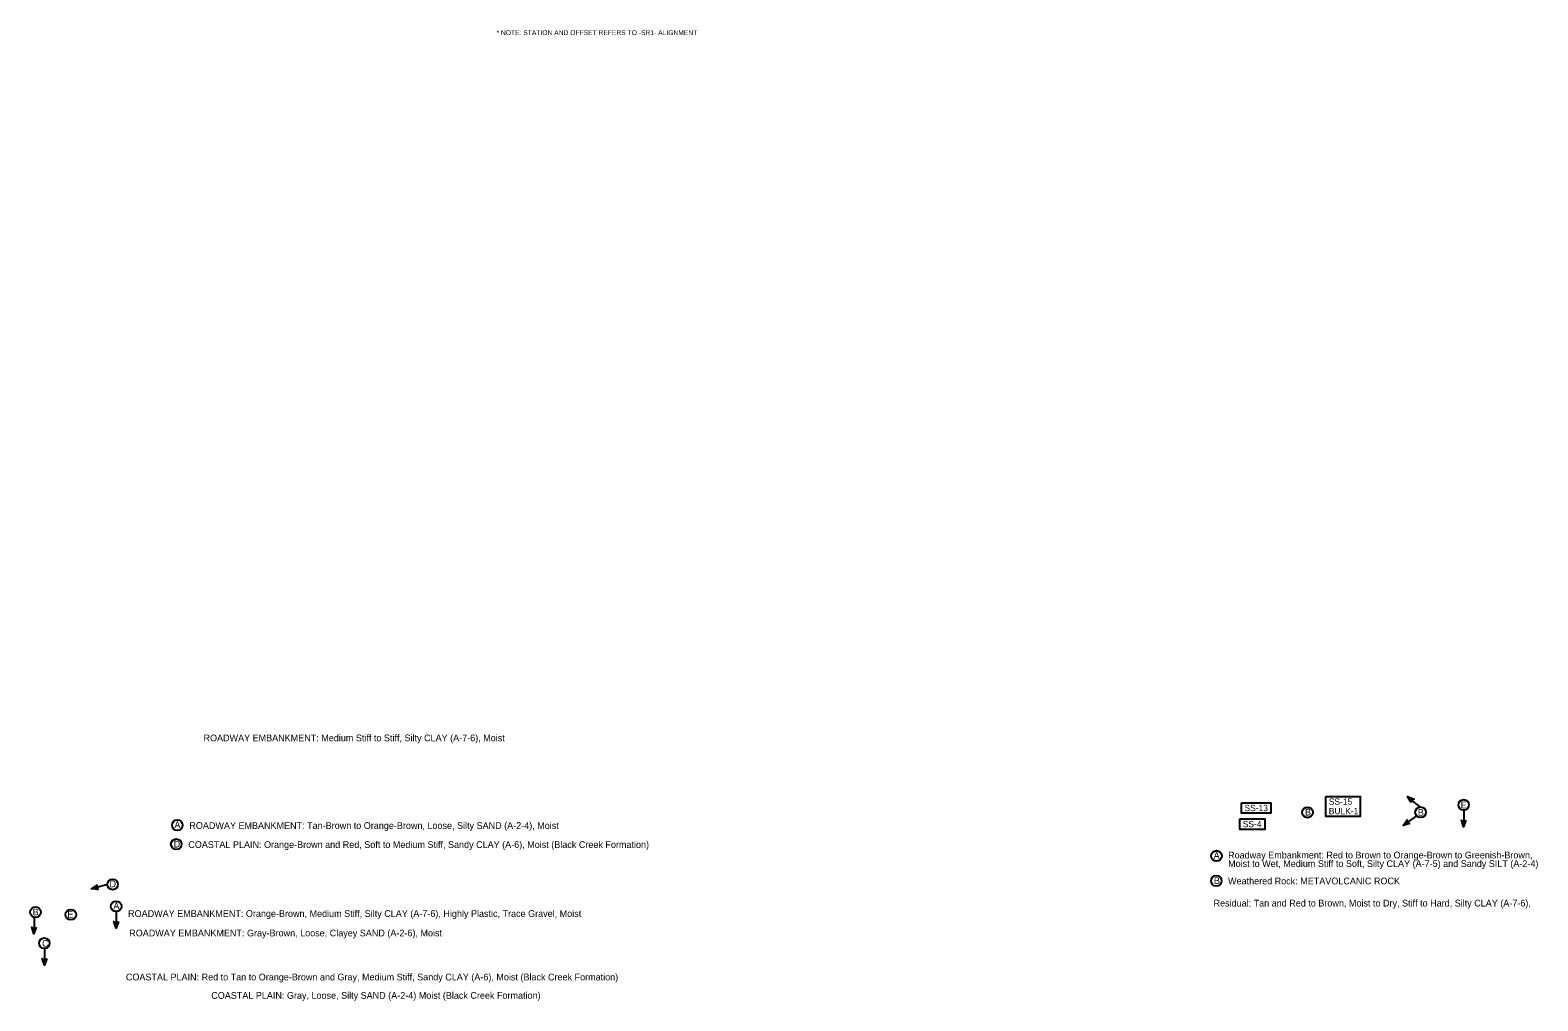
# Model space of a CAD drawing. Extents: x -516 to 303, y -10 to 5017.
# Drawn here: x -515.5 to -180.3, y -0.7 to 215.2 of the extents above; entities that cross this region are included whole.
import ezdxf

# ---------------------------------------------------------------- set-up
doc = ezdxf.new("R2010")
doc.units = 0
for name, color, linetype in [('Misc Plan Tools Cell', 7, 'Continuous'), ('Prop DirtTable_ Soil Test Results - Tx (Sample Data)', 7, 'Continuous'), ('Prop Road Sect_ Boring - Header (Sample Box + Tx)', 7, 'Continuous'), ('Prop Road Sect_ Material - Bubble + Leader + Bubble Tx', 7, 'Continuous'), ('Prop Road Sect_ Material - Tx (Composite Desc)', 7, 'Continuous')]:
    doc.layers.add(name, color=color, linetype=linetype)

msp = doc.modelspace()

# ---------------------------------------------------------------- linework, layer by layer
at = {"layer": 'Misc Plan Tools Cell'}
for points in [[(-208.4, 43.36), (-209.26, 44.69), (-207.77, 44.14), (-208.48, 44.07)], [(-208.71, 38.74), (-210.22, 38.26), (-209.3, 39.55), (-209.41, 38.85)], [(-196.25, 39.46), (-196.77, 37.97), (-197.25, 39.47), (-196.76, 38.97)], [(-500.33, 24.07), (-501.91, 24.15), (-500.6, 25.03), (-500.95, 24.42)], [(-495.89, 16.9), (-496.41, 15.41), (-496.89, 16.92), (-496.4, 16.41)], [(-514.16, 15.64), (-514.67, 14.15), (-515.16, 15.66), (-514.66, 15.15)], [(-511.84, 8.7), (-512.36, 7.2), (-512.84, 8.71), (-512.35, 8.2)]]:
    msp.add_lwpolyline(points, close=True, dxfattribs=at)
at = {"layer": 'Prop Road Sect_ Boring - Header (Sample Box + Tx)'}
for points in [[(-227.43, 44.7), (-219.77, 44.7), (-219.77, 40.25), (-227.43, 40.25)], [(-246.17, 43.29), (-239.61, 43.29), (-239.61, 40.98), (-246.17, 40.98)], [(-246.56, 39.72), (-240.96, 39.72), (-240.96, 37.41), (-246.56, 37.41)]]:
    msp.add_lwpolyline(points, close=True, dxfattribs=at)
at = {"layer": 'Prop Road Sect_ Material - Bubble + Leader + Bubble Tx'}
for p, q in [((-206.37, 42.37), (-208.48, 44.07)), ((-207.22, 40.44), (-209.41, 38.85)), ((-196.73, 41.67), (-196.76, 38.97)), ((-498.34, 25.15), (-500.95, 24.42)), ((-514.63, 17.86), (-514.66, 15.15)), ((-496.36, 19.12), (-496.4, 16.41)), ((-512.31, 10.91), (-512.35, 8.2))]:
    msp.add_line(p, q, dxfattribs=at)
for centre in [(-196.76, 42.85), (-231.49, 41.19), (-206.33, 41.21), (-482.79, 38.34), (-483.02, 34.1), (-251.71, 31.5), (-251.76, 25.97), (-497.17, 25.16), (-514.34, 19), (-496.4, 20.29), (-506.48, 18.44), (-512.37, 12.08)]:
    msp.add_circle(centre, 1.18, dxfattribs=at)

# ---------------------------------------------------------------- texts
at = {"layer": 'Prop DirtTable_ Soil Test Results - Tx (Sample Data)'}
msp.add_text('* NOTE: STATION AND OFFSET REFERS TO -SR1- ALIGNMENT', height=1.08, dxfattribs=at).set_placement((-411.83, 214.09))
at = {"layer": 'Prop Road Sect_ Boring - Header (Sample Box + Tx)'}
for s, p in [('SS-15', (-226.75, 42.88)), ('SS-13', (-245.49, 41.46)), ('BULK-1', (-226.75, 40.78)), ('SS-4', (-245.88, 37.89))]:
    msp.add_text(s, height=1.4, dxfattribs=at).set_placement(p)
at = {"layer": 'Prop Road Sect_ Material - Tx (Composite Desc)'}
for s, p in [('ROADWAY EMBANKMENT: Medium Stiff to Stiff, Silty CLAY (A-7-6), Moist', (-476.97, 57)), ('B', (-232.04, 40.49)), ('B', (-206.95, 40.42)), ('E', (-197.44, 42.06)), ('A', (-483.44, 37.68)), ('ROADWAY EMBANKMENT: Tan-Brown to Orange-Brown, Loose, Silty SAND (A-2-4), Moist', (-480.12, 37.51)), ('D', (-483.62, 33.37)), ('COASTAL PLAIN: Orange-Brown and Red, Soft to Medium Stiff, Sandy CLAY (A-6), Moist (Black Creek Formation)', (-480.35, 33.27)), ('A', (-252.37, 30.86)), ('Roadway Embankment: Red to Brown to Orange-Brown to Greenish-Brown, ', (-249.14, 30.94)), ('Moist to Wet, Medium Stiff to Soft, Silty CLAY (A-7-5) and Sandy SILT (A-2-4)', (-249.14, 29.04)), ('D', (-497.86, 24.53)), ('B', (-252.31, 25.27)), ('Weathered Rock: METAVOLCANIC ROCK', (-249.15, 25.17)), ('A', (-497.02, 19.66)), ('Residual: Tan and Red to Brown, Moist to Dry, Stiff to Hard, Silty CLAY (A-7-6), ', (-252.38, 20.25)), ('B', (-514.97, 18.26)), ('E', (-507.24, 17.78)), ('ROADWAY EMBANKMENT: Orange-Brown, Medium Stiff, Silty CLAY (A-7-6), Highly Plastic, Trace Gravel, Moist', (-493.74, 17.93)), ('ROADWAY EMBANKMENT: Gray-Brown, Loose, Clayey SAND (A-2-6), Moist', (-493.49, 13.6)), ('C', (-512.86, 11.3)), ('COASTAL PLAIN: Red to Tan to Orange-Brown and Gray, Medium Stiff, Sandy CLAY (A-6), Moist (Black Creek Formation)', (-494.23, 3.81)), ('COASTAL PLAIN: Gray, Loose, Silty SAND (A-2-4) Moist (Black Creek Formation)', (-475.25, -0.28))]:
    msp.add_text(s, height=1.5, dxfattribs=at).set_placement(p)

doc.saveas('drawing.dxf')
